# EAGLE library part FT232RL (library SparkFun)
USB UART FT232RL 4th Generation USB UART (USB <-> Serial) Controller. Spark Fun Electronics SKU : IC-FT232RL
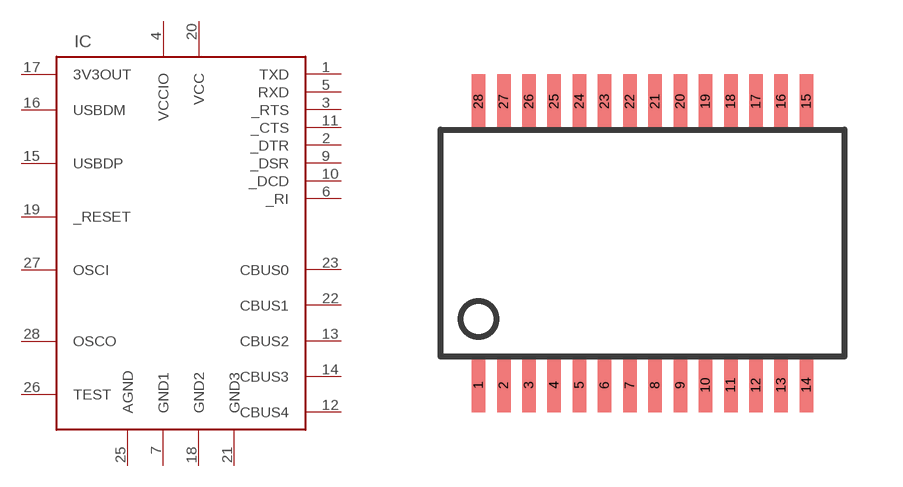
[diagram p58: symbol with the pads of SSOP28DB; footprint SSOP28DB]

Designator prefix IC

## FT232RL  [SSOP28DB]
1  TXD  out
2  _DTR  out
3  _RTS  out
4  VCCIO  pwr
5  RXD  in
6  _RI  in
7  GND1  pwr
9  _DSR  in
10  _DCD  in
11  _CTS  in
12  CBUS4
13  CBUS2
14  CBUS3
15  USBDP
16  USBDM
17  3V3OUT  out
18  GND2  pwr
19  _RESET  in
20  VCC  pwr
21  GND3  pwr
22  CBUS1
23  CBUS0
25  AGND  pwr
26  TEST  in
27  OSCI  in
28  OSCO  out

## Footprint SSOP28DB (pad centres in mm)
Small Shrink Outline Package
smd 0.348 x 1.397: 1 -4.225,-3.656; 2 -3.575,-3.656; 3 -2.925,-3.656; 4 -2.275,-3.656; 5 -1.625,-3.656; 6 -0.975,-3.656; 7 -0.325,-3.656; 8 0.325,-3.656; 9 0.975,-3.656; 10 1.625,-3.656; 11 2.275,-3.656; 12 2.925,-3.656; 13 3.575,-3.656; 14 4.225,-3.656; 15 4.225,3.656; 16 3.575,3.656; 17 2.925,3.656; 18 2.275,3.656; 19 1.625,3.656; 20 0.975,3.656; 21 0.325,3.656; 22 -0.325,3.656; 23 -0.975,3.656; 24 -1.625,3.656; 25 -2.275,3.656; 26 -2.925,3.656; 27 -3.575,3.656; 28 -4.225,3.656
